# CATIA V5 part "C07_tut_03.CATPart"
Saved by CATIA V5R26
Part number: Part1
Bounding box of the stored display mesh (mm): x 0 to 108, y -53 to 53, z -53 to 53
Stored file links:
  D:\_Deepak\CATIA\CATIA V5-6R2016_Deepak\Resources\Tutorial Files\Tutorials\c07_catia_v5_6r2016_tut\C07_tut_03.CATPart
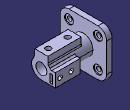
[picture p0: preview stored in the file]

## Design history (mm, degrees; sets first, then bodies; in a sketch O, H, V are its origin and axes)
Body1 (main body)
  Sketch1 on yz-plane, origin (0, 0, 0), H (0, 1, 0), V (0, 0, 1)
    line L1 (53, 33) -> (53, -33)
    line L2 (33, -53) -> (-33, -53)
    line L3 (-53, -33) -> (-53, 33)
    line L4 (-33, 53) -> (33, 53)
    point P1 (53, 53)
    point P2 (53, -53)
    point P3 (-53, -53)
    arc A1 centre (33, 33) radius 20 from (53, 33) to (33, 53) ccw
    arc A2 centre (33, -33) radius 20 from (53, -33) to (33, -53) cw
    arc A3 centre (-33, -33) radius 20 from (-33, -53) to (-53, -33) cw
    arc A4 centre (-33, 33) radius 20 from (-53, 33) to (-33, 53) cw
    distance P1 P2 = 106
    radius A1 = 20
    distance P2 P3 = 106
    radius A2 = 20
    radius A3 = 20
    radius A4 = 20
    vertical: L1 V, L3 V
    horizontal: L2 H, L4 H
    equidistance: L1 L3 O, L2 L4 O
    coincidence: L1 P1, L4 P1, L1 P2, L2 P2, L2 P3, L3 P3
    tangency: A1 L1, A1 L4, A2 L1, A2 L2, A3 L2, A3 L3, A4 L3, A4 L4
  Pad1: profile Sketch1, direction (1, 0, 0), length 12
  Sketch2 on face of Pad1, origin (12, 0, 0), H (0, 1, 0), V (0, 0, 1)
    circle A1 centre (0, 0) radius 22
    radius A1 = 22
  Pad2: profile Sketch2, direction (1, 0, 0), length 96
  Sketch3 on face of Pad2, origin (108, 0, 0), H (0, 1, 0), V (0, 0, 1)
    point P1 (-15, 16.0935)
    line L1 (-15, 16.0935) -> (-15, 32)
    line L2 (-15, 32) -> (15, 32)
    line L3 (15, 32) -> (15, 16.0935)
    point P4 (15, 16.0935)
    axis line L4 (0, 0) -> (0, 32)
    point P5 (0, 32)
    reference projected circle E1 centre (0, 0) radius 22 from edge [face of Pad2 | face of Pad2]
    reference projected circle E2 centre (0, 0) radius 22 from edge [face of Pad2 | face of Pad2]
    projected circle E3 centre (0, 0) radius 22 from edge [face of Pad2 | face of Pad2]
    projected arc E4 centre (0, 0) radius 22 from (15, 16.0935) to (-15, 16.0935) ccw from edge [face of Pad2 | face of Pad2]
    length L2 = 30
    distance H L2 = 32
    vertical: L1 V, L3 V, L4 V
    horizontal: L2 H
    midpoint: P5 L2
    coincidence: P4 E1, P1 E2
  Pad3: profile Sketch3, direction (-1, 0, 0), length 76
  Sketch4 on face of Pad2, origin (108, 0, 0), H (0, 1, 0), V (0, 0, 1)
    point P1 (0, -22)
    line L1 (0, -22) -> (32, -22)
    line L2 (32, -22) -> (32, 8)
    line L3 (32, 8) -> (20.4939, 8)
    point P4 (20.4939, 8)
    reference projected circle E1 centre (0, 0) radius 22 from edge of Pad2
    reference projected circle E2 centre (0, 0) radius 22 from edge [face of Pad2 | face of Pad2]
    reference projected circle E3 centre (0, 0) radius 22 from edge [face of Pad2 | face of Pad2]
    projected arc E4 centre (0, 0) radius 22 from (-15, 16.0935) to (15, 16.0935) ccw from edge of Pad3
    projected arc E5 centre (0, 0) radius 22 from (0, -22) to (20.4939, 8) ccw from edge of Pad3
    length L2 = 30
    distance V L2 = 32
    coincidence: P1 V, P4 E1, P1 E2
    horizontal: L1 H, L3 H
    vertical: L2 V
    tangency: L1 E3
  Pad4: profile Sketch4, direction (-1, 0, 0), length 57
  Sketch5 on face of Pad2, origin (108, 0, 0), H (0, 1, 0), V (0, 0, 1)
    line L1 (19, 1) -> (25, 1)
    line L2 (25, 1) -> (25, -18)
    line L3 (25, -18) -> (19, -18)
    line L4 (19, -18) -> (19, 1)
    reference projected line E1 (53, -33) -> (53, 33) from edge [face of Pad1 | face of Pad1]
    reference projected line E2 (-33, -53) -> (33, -53) from edge [face of Pad1 | face of Pad1]
    length L3 = 6
    length L2 = 19
    distance L4 E1 = 34
    distance L3 E2 = 35
    horizontal: L1 H, L3 H
    vertical: L2 V, L4 V
  Pocket1: profile Sketch5, direction (-1, 0, 0), length 50
  Sketch6 on face of Pad2, origin (108, 0, 0), H (0, 1, 0), V (0, 0, 1)
    point P1 (0, 0)
    coincidence: P1 O
  Hole1: placed by Sketch6, at (108, 0, 0) direction (-1, 0, 0), diameter 25, depth 82
  Sketch7 on face of Pad3, origin (90.7325, -5.9449, 32), H (1, 0, 0), V (0, 1, 0)
    point P1 (1.2675, 5.9449)
    reference projected line E1 (17.2675, -9.0551) -> (-58.7325, -9.0551) from edge [face of Pad3 | face of Pad3]
    reference projected line E2 (17.2675, 20.9449) -> (17.2675, -9.0551) from edge [face of Pad3 | face of Pad3]
    distance P1 E1 = 15
    distance P1 E2 = 16
  Hole2: placed by Sketch7, at (92, 0, 32) direction (0, 0, -1), diameter 12, depth 33.0037, threaded, thread diameter 13.2, thread depth 10, pitch 1
  RectPattern1: of Hole2, direction 1 instances 2, spacing 44, along edge [face of Pad3 | face of Pad3]
  Sketch8 on face of Pad4, origin (86.2721, 32, -2.7131), H (1, 0, 0), V (0, 0, -1)
    point P1 (10.7279, 4.2869)
    reference projected line E1 (21.7279, 19.2869) -> (-35.2721, 19.2869) from edge [face of Pad4 | face of Pad4]
    reference projected line E2 (21.7279, 19.2869) -> (21.7279, -10.7131) from edge [face of Pad4 | face of Pad4]
    distance P1 E1 = 15
    distance E2 P1 = 11
  Hole3: placed by Sketch8, at (97, 32, -7) direction (0, -1, 0), diameter 10, through (limit type 6)
  RectPattern2: of Hole3, direction 1 instances 2, spacing 25, along edge [face of Pad4 | face of Pad4], direction 2 instances 2, spacing 76
  Sketch9 on face of Pad1, origin (12, -36.1764, 22.8739), H (0, 1, 0), V (0, 0, 1)
    point P1 (3.1764, -55.8739)
    reference projected line E1 (-16.8236, 10.1261) -> (-16.8236, -55.8739) from edge [face of Pad1 | face of Pad1]
    reference projected line E2 (3.1764, -75.8739) -> (69.1764, -75.8739) from edge [face of Pad1 | face of Pad1]
    distance P1 E1 = 20
    distance E2 P1 = 20
  Hole4: placed by Sketch9, at (12, -33, -33) direction (-1, 0, 0), diameter 10, through (limit type 3), counterbore diameter 20, counterbore depth 2
  RectPattern3: of Hole4, direction 1 instances 2, spacing 66, along edge [face of Pad1 | face of Pad1], direction 2 instances 2, spacing 66, along edge [face of Pad1 | face of Pad1] reversed
  Fillet1: radius 15, on edge [face of Pad3 | face of Pad2]
  Fillet2: radius 5, on edge [face of Pad2 | face of Pad3]; edge [face of Pad2 | face of Pad4]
